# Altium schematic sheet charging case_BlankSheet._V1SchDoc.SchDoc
size 431 x 279 mm; Date: Not shown in title block; ApprovedBy: Not shown in title block; CheckedBy: Not shown in title block; Author: Not shown in title block; CompanyName: Not shown in title block; Engineer: Not shown in title block; Organization: Not shown in title block; Address1: Not shown in title block; Address2: Not shown in title block; Address3: Not shown in title block; Address4: Not shown in title block; DocumentNumber: 1; Revision: Use project parameter SCH_Rev; SheetNumber: 2; SheetTotal: 3; PageSetup: Record=PageOptions¦CenterHorizontal=True¦CenterVertical=True¦PrintScale=1.00¦XCorrection=1.00¦YCorrection=1.00¦PrintKind=0¦BorderSize=5000000¦LeftOffset=0¦BottomOffset=0¦Orientation=2¦PaperLength=1000¦PaperWidth=1000¦Scale=100¦PaperSource=15¦PrintQuality=600¦MediaType=1¦DitherType=10¦PaperKind=Letter¦PrintScaleMode=1
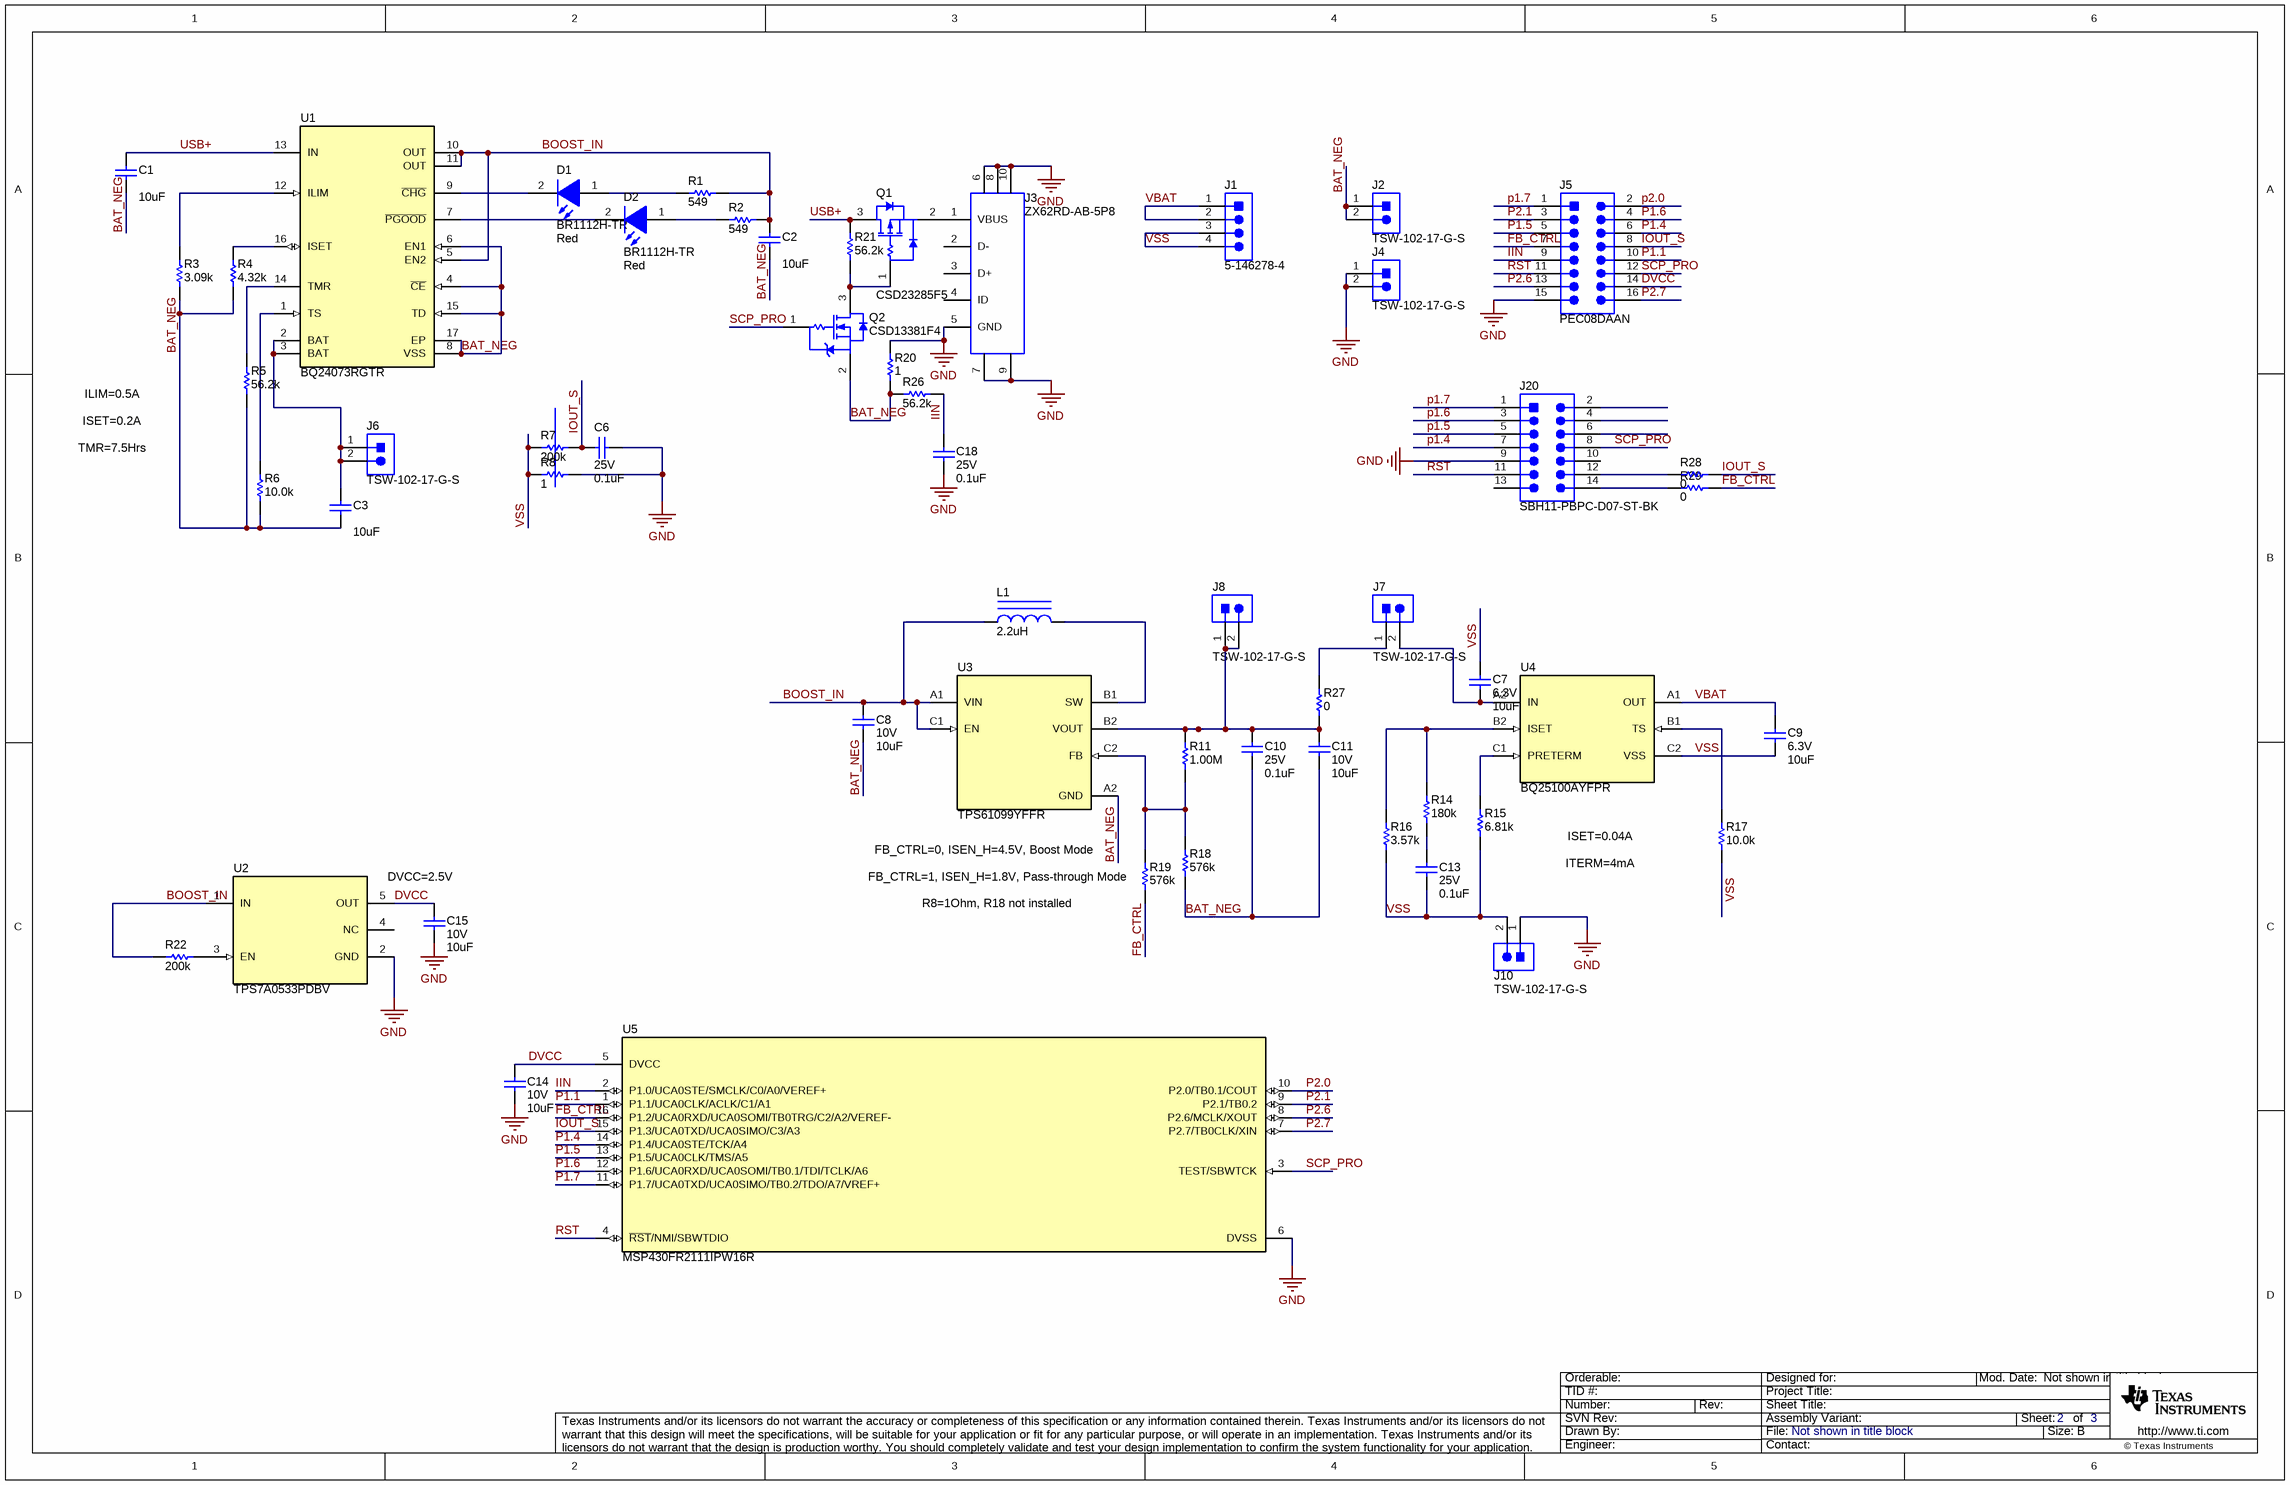
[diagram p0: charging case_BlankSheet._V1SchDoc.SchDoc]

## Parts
C1  ValueDisplayed: 10uF  [0603]  (hidden comment: GRM188Z71A106MA73D)
C2  ValueDisplayed: 10uF  [0603]  (hidden comment: GRM188Z71A106MA73D)
C3  ValueDisplayed: 10uF  [0603]  (hidden comment: GRM188Z71A106MA73D)
C6  VDC_V: 25V  ValueDisplayed: 0.1uF  [0603]  (hidden comment: 06033D104KAT2A)
C7  VDC_V: 6.3V  ValueDisplayed: 10uF  [0402_070]  (hidden comment: C1005X5R0J106M050BC)
C8  VDC_V: 10V  ValueDisplayed: 10uF  [0603]  (hidden comment: GRM188Z71A106MA73D)
C9  VDC_V: 6.3V  ValueDisplayed: 10uF  [0402_070]  (hidden comment: C1005X5R0J106M050BC)
C10  VDC_V: 25V  ValueDisplayed: 0.1uF  [0603]  (hidden comment: 06033D104KAT2A)
C11  VDC_V: 10V  ValueDisplayed: 10uF  [0603]  (hidden comment: GRM188Z71A106MA73D)
C13  VDC_V: 25V  ValueDisplayed: 0.1uF  [0402]  (hidden comment: GRM155R61E104KA87D)
C14  VDC_V: 10V  ValueDisplayed: 10uF  [0603]  (hidden comment: GRM188Z71A106MA73D)
C15  VDC_V: 10V  ValueDisplayed: 10uF  [0603]  (hidden comment: GRM188Z71A106MA73D)
C18  VDC_V: 25V  ValueDisplayed: 0.1uF  [0603]  (hidden comment: 06033D104KAT2A)
D1  BR1112H-TR  value Red  [BR1112H_Red]
D2  BR1112H-TR  value Red  [BR1112H_Red]
J1  5-146278-4  [TE_5-146278-4]
J2  TSW-102-17-G-S  [Samtec_TSW-102-17-x-S]
J3  ZX62RD-AB-5P8  [Hirose_ZX62RD-AB-5P8]
J4  TSW-102-17-G-S  [Samtec_TSW-102-17-x-S]
J5  PEC08DAAN  [Sullins_xxC08DAAN]
J6  TSW-102-17-G-S  [Samtec_TSW-102-17-x-S]
J7  TSW-102-17-G-S  [Samtec_TSW-102-17-x-S]
J8  TSW-102-17-G-S  [Samtec_TSW-102-17-x-S]
J10  TSW-102-17-G-S  [Samtec_TSW-102-17-x-S]
J20  SBH11-PBPC-D07-ST-BK  [CONN_SBH11-PBPC-D07-ST-BK]
L1  ValueDisplayed: 2.2uH  [DFE252012C]  (hidden comment: DFE252012F-2R2M=P2)
Q1  CSD23285F5  [YJK0003A]
Q2  CSD13381F4  [YJC0003A]
R1  ValueDisplayed: 549  [0603]  (hidden comment: RT0603DRE07549RL)
R2  ValueDisplayed: 549  [0603]  (hidden comment: RT0603DRE07549RL)
R3  ValueDisplayed: 3.09k  [0603]  (hidden comment: RC0603FR-073K09L)
R4  ValueDisplayed: 4.32k  [0603]  (hidden comment: RC0603FR-074K32L)
R5  ValueDisplayed: 56.2k  [0603]  (hidden comment: RC0603FR-0756K2L)
R6  ValueDisplayed: 10.0k  [0603]  (hidden comment: RC0603FR-0710KL)
R7  ValueDisplayed: 200k  [0603]  (hidden comment: RG1608P-204-B-T5)
R8  ValueDisplayed: 1  [1206]  (hidden comment: CRM1206-JW-1R0ELF)
R11  ValueDisplayed: 1.00M  [0603]  (hidden comment: MCT06030C1004FP500)
R14  ValueDisplayed: 180k  [0402]  (hidden comment: RC0402FR-07180KL)
R15  ValueDisplayed: 6.81k  [0402]  (hidden comment: RC0402FR-076K81L)
R16  ValueDisplayed: 3.57k  [0402]  (hidden comment: RC0402FR-073K57L)
R17  ValueDisplayed: 10.0k  [0402]  (hidden comment: RC0402FR-0710KL)
R18  ValueDisplayed: 576k  [0603]  (hidden comment: RC0603FR-07576KL)
R19  ValueDisplayed: 576k  [0603]  (hidden comment: RC0603FR-07576KL)
R20  ValueDisplayed: 1  [1206]  (hidden comment: CRM1206-JW-1R0ELF)
R21  ValueDisplayed: 56.2k  [0603]  (hidden comment: RC0603FR-0756K2L)
R22  ValueDisplayed: 200k  [0603]  (hidden comment: RG1608P-204-B-T5)
R26  ValueDisplayed: 56.2k  [0603]  (hidden comment: RC0603FR-0756K2L)
R27  ValueDisplayed: 0  [0603]  (hidden comment: RMCF0603ZT0R00)
R28  ValueDisplayed: 0  [0603]  (hidden comment: RMCF0603ZT0R00)
R29  ValueDisplayed: 0  [0603]  (hidden comment: RMCF0603ZT0R00)
U1  PartNumber: BQ24073RGTR  [RGT0016C]  (hidden comment: BQ24230RGTR)
U2  TPS7A0533PDBV  [DBV0005A_N]
U3  TPS61099YFFR  [YFF0006AFAD]
U4  BQ25100AYFPR  [YFP0006AFAV]
U5  MSP430FR2111IPW16R  [PW0016A_L]

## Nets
GND: C6.1 C14.2 C15.2 C18.2 J3.5(GND) J3.6 J3.7 J3.8 J3.9 J3.10 J4.1 J4.2 J5.15 J10.1 J20.9 R8.2 R20.2 U2.2(GND) U5.6(DVSS)
BAT_NEG: C1.2 C2.2 C3.2 C8.2 C10.2 C11.2 J2.1 J2.2 Q2.2(S) R3.1 R4.1 R5.1 R6.1 R18.1 R20.1 R26.2 U1.4(~{CE}) U1.6(EN1) U1.8(VSS) U1.15(TD) U1.17(EP) U3.A2(GND)
BOOST_IN: C2.1 C8.1 L1.1 R1.1 R2.1 R22.2 U1.5(EN2) U1.10(OUT) U1.11(OUT) U2.1(IN) U3.A1(VIN) U3.C1(EN)
DVCC: C14.1 C15.1 J5.14 U2.5(OUT) U5.5(DVCC)
FB_CTRL: J5.7 R19.1 R29.1 U5.16(P1.2/UCA0RXD/UCA0SOMI/TB0TRG/C2/A2/VEREF-)
IIN: C18.1 J5.9 R26.1 U5.2(P1.0/UCA0STE/SMCLK/C0/A0/VEREF+)
IOUT_S: C6.2 J5.8 R7.1 R28.1 U5.15(P1.3/UCA0TXD/UCA0SIMO/C3/A3)
P1.1: J5.10 U5.1(P1.1/UCA0CLK/ACLK/C1/A1)
P1.4: J5.6 J20.7 U5.14(P1.4/UCA0STE/TCK/A4)
P1.5: J5.5 J20.5 U5.13(P1.5/UCA0CLK/TMS/A5)
P1.6: J5.4 J20.3 U5.12(P1.6/UCA0RXD/UCA0SOMI/TB0.1/TDI/TCLK/A6)
P1.7: J5.1 J20.1 U5.11(P1.7/UCA0TXD/UCA0SIMO/TB0.2/TDO/A7/VREF+)
P2.0: J5.2 U5.10(P2.0/TB0.1/COUT)
P2.1: J5.3 U5.9(P2.1/TB0.2)
P2.6: J5.13 U5.8(P2.6/MCLK/XOUT)
P2.7: J5.16 U5.7(P2.7/TB0CLK/XIN)
RST: J5.11 J20.11 U5.4(~{RST}/NMI/SBWTDIO)
SCP_PRO: J5.12 J20.8 Q2.1(G) U5.3(TEST/SBWTCK)
USB+: C1.1 Q1.3(D) R21.2 U1.13(IN)
VBAT: C9.1 J1.1 J1.2 U4.A1(OUT)
VSS: C7.1 C9.2 C13.2 J1.3 J1.4 J10.2 R7.2 R8.1 R15.1 R16.1 R17.1 U4.C2(VSS)
NetC3_1: C3.1 J6.1 J6.2 U1.2(BAT) U1.3(BAT)
NetC7_2: C7.2 J7.2 U4.A2(IN)
NetC10_1: C10.1 C11.1 J8.1 J8.2 R11.2 R27.1 U3.B2(VOUT)
NetC13_1: C13.1 R14.1
NetD1_1: D1.1(A) R1.2
NetD1_2: D1.2(K) U1.9(~{CHG})
NetD2_1: D2.1(A) R2.2
NetD2_2: D2.2(K) U1.7(~{PGOOD})
NetJ3_1: J3.1(VBUS) Q1.2(S)
NetJ7_1: J7.1 R27.2
NetJ20_12: J20.12 R28.2
NetJ20_14: J20.14 R29.2
NetL1_2: L1.2 U3.B1(SW)
NetQ1_1: Q1.1(G) Q2.3(D) R21.1
NetR3_2: R3.2 U1.12(ILIM)
NetR4_2: R4.2 U1.16(ISET)
NetR5_2: R5.2 U1.14(TMR)
NetR6_2: R6.2 U1.1(TS)
NetR11_1: R11.1 R18.2 R19.2 U3.C2(FB)
NetR14_2: R14.2 R16.2 U4.B2(ISET)
NetR15_2: R15.2 U4.C1(PRETERM)
NetR17_2: R17.2 U4.B1(TS)
NetR22_1: R22.1 U2.3(EN)

Not connected (* = marked no-connect by the designer): J3 2(D-) 3(D+) 4(ID); J20 2 4 6 10 13; U2 4(NC)

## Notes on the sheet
- ILIM=0.5A
- ISET=0.2A
- TMR=7.5Hrs
- ISET=0.04A
- DVCC=2.5V
- FB_CTRL=0, ISEN_H=4.5V, Boost Mode
- (near R19) FB_CTRL=1, ISEN_H=1.8V, Pass-through Mode
- R8=1Ohm, R18 not installed
- ITERM=4mA

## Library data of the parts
C1 = CMP-0007497-5: CAP, CERM, 10 uF, 10 V, +/- 20%, X7R, 0603; Manufacturer: MuRata; TaMin_C: -55°C; Polarized: N; SizeAreaWB_mm2: 4.68; Value1: Unknown; U/M: EA; Value: 10uF; TaMax_C: 125°C; SizeZ_mm: 1; SizeX_mm: 1.6; SizeY_mm: 0.8; Value2: 10V; SizeArea_mm2: 1.28; Cap_F: 10µF; AEC Category: Q200
C2 C3 = CMP-0007497-5: CAP, CERM, 10 uF, 10 V, +/- 20%, X7R, 0603; Manufacturer: MuRata; TaMin_C: -55°C; Polarized: N; SizeAreaWB_mm2: 4.68; Value1: Unknown; U/M: EA; Value: 10uF; TaMax_C: 125°C; SizeZ_mm: 1; SizeX_mm: 1.6; SizeY_mm: 0.8; Value2: 10V; SizeArea_mm2: 1.28; CompType: Capacitor; Cap_F: 10µF; AEC Category: Q200
C6 C10 C18 = CMP-0006758-5: CAP, CERM, 0.1 uF, 25 V, +/- 10%, X5R, 0603; Manufacturer: AVX; TaMin_C: -55°C; ESR_ohm: 0.048; Polarized: N; SizeAreaWB_mm2: 4.68; Value1: 0.048 ohm; U/M: EA; Value: 0.1uF; TaMax_C: 85°C; SizeZ_mm: 1; SizeX_mm: 1.6; SizeY_mm: 0.8; SizeArea_mm2: 1.28; Cap_F: 100nF; IRMS_A: 5.3dA; AEC Category: Q200
C7 = CMP-0006257-2: CAP, CERM, 10 uF, 6.3 V, +/- 20%, X5R, 0402; Manufacturer: TDK; TaMin_C: -55°C; ESR_ohm: 3.019m; Polarized: N; SizeAreaWB_mm2: 3; Value1: 0.003019 ohm; U/M: EA; Value: 10uF; TaMax_C: 85°C; SizeZ_mm: 0.7; SizeX_mm: 1; SizeY_mm: 0.5; Cap_F: 10µF; IRMS_A: 2.87803A; AEC Category: Q200
C8 C11 C14 C15 = CMP-0007497-5: CAP, CERM, 10 uF, 10 V, +/- 20%, X7R, 0603; Manufacturer: MuRata; TaMin_C: -55°C; Polarized: N; SizeAreaWB_mm2: 4.68; Value1: Unknown; U/M: EA; Value: 10uF; TaMax_C: 125°C; SizeZ_mm: 1; SizeX_mm: 1.6; SizeY_mm: 0.8; SizeArea_mm2: 1.28; Cap_F: 10µF; AEC Category: Q200
C9 = CMP-0006257-2: CAP, CERM, 10 uF, 6.3 V, +/- 20%, X5R, 0402; Manufacturer: TDK; TaMin_C: -55°C; ESR_ohm: 3.019m; Polarized: N; SizeAreaWB_mm2: 3; Value1: 0.003019 ohm; U/M: EA; Value: 10uF; TaMax_C: 85°C; SizeZ_mm: 0.7; SizeX_mm: 1; SizeY_mm: 0.5; CompType: Capacitor; Cap_F: 10µF; IRMS_A: 2.87803A; AEC Category: Q200
C13 = CMP-0006607-2: CAP, CERM, 0.1 uF, 25 V, +/- 10%, X5R, 0402; Manufacturer: MuRata; TaMin_C: -55°C; Polarized: N; SizeAreaWB_mm2: 3; Value1: Unknown; U/M: EA; Value: 0.1uF; TaMax_C: 85°C; SizeZ_mm: 0.6; SizeX_mm: 1; SizeY_mm: 0.5; CompType: Capacitor; Cap_F: 100nF; AEC Category: Q200
D1 D2 = CMP-0067678-1: LED, Red, SMD; Manufacturer: Stanley Electric Co., LTD; Io_A: 20mA; Power_TotalModule: 57.5mW; Green_Lifecycle: Not Set; SizeAreaWB_mm2: 6.75; Vr_V: 4V; Tjmax_C: 85°C; Green_REACh: Incomplete; Value1: 0.0575W; U/M: EA; Angle: 150.0; SizeZ_mm: 0.9; SizeX_mm: 2.0; SizeY_mm: 1.25; Ir_A: 100µA; Vf_V: 1.7V; SizeArea_mm2: 2.5
J1 = CMP-0054950-1: Header, 100mil, 4x1, Tin, TH; Manufacturer: TE Connectivity; CNHeader: TRUE; Green_Lifecycle: Active; Green_REACh: Passed; CT: FALSE
J2 J4 J6-J8 J10 = CMP-0077742-1: Header, 2.54mm, 2x1, Gold, TH; Manufacturer: Samtec; Pitch_mm: 2.54; Gender: Male; Cert_CSA: Y; Shrouded: N; Row_Count: 1
J3 = CMP-0075126-1: Connector, Receptacle, Micro-USB Type AB, R/A, Bottom Mount SMT; Manufacturer: Hirose Electric Co. Ltd.; CNHeader: False; Gender: Female; CompType: USB; Row_Count: 1; Pitch_mm: 0.65; CT: True
J5 = CMP-0054579-1: Header, 2.54 mm, 8x2, Tin, Vertical, TH; Manufacturer: Sullins Connector Solutions; CNHeader: TRUE; Current_A: 3A; Green_Lifecycle: Not Set; Shrouded: N; Gender: Male; Green_REACh: Incomplete; Voltage_V: 1.8kV; Row_Count: 2; RowSpacing_mm: 2.54; CT: FALSE; Cert_UL: Y
J20 = CMP-0054695-1: Header (shrouded), 100 mil, 7x2, Gold, TH; Manufacturer: Sullins Connector Solutions; CT: FALSE; Green_REACh: Incomplete; Green_Lifecycle: Not Set
L1 = CMP-0058932-1: Inductor, Shielded, Powdered Iron, 2.2 uH, 2.3 A, 0.082 ohm, SMD; Manufacturer: MuRata Toko; Isat: 3.3A @ 30% inductance drop; Irms: 2.3A @ 40C rise; SizeAreaWB_mm2: 11.84; DCR_ohm: 0.082; Value: 2.2uH; Imax_A: 2.3A; SizeZ_mm: 1.2; SizeX_mm: 2.7; SizeY_mm: 2.2; SizeArea_mm2: 5.94; Ind_H: 2.2µH; AEC Qualified: N; AEC Category: Q200
Q1 = CMP-0000021-2: MOSFET, P-CH, -12 V, -3.3 A, YJK0003A (PICOSTAR-3); Alternate Manufacturer: None; Manufacturer: Texas Instruments; SizeZ_mm: 0.35; ChType: P; Value2: 3.2 nC; Value1: 0.03; VdsMax_V: -12V; SizeX_mm: 1.49; SizeY_mm: 0.73; Vgs_V: -6V; AEC Qualified: N; Value: -12V; Rdson45_ohm: 0.035; SizeArea_mm2: 1.0877; AEC Category: Q101; IdsMax_A: -3.3A; SizeAreaWB_mm2: 4.3077; U/M: EA; QgTyp_nC: 3.2
Q2 = CMP-0000197-1: MOSFET, N-CH, 12 V, 2.1 A, YJC0003A (PICOSTAR-3); Alternate Manufacturer: None; Manufacturer: Texas Instruments; SizeZ_mm: 0.35; ChType: N; Value2: 1.06 nC; Value1: 0.1; VdsMax_V: 12V; SizeX_mm: 1.035; SizeY_mm: 0.635; Vgs_V: 8V; Value: 12V; Rdson45_ohm: 1.4d; SizeArea_mm2: 0.657225; AEC Category: Q101; IdsMax_A: 2.1A; SizeAreaWB_mm2: 3.327225; U/M: EA; QgTyp_nC: 1.06
R1 = CMP-0025400-3: RES, 549, 0.5%, 0.1 W, 0603; Manufacturer: Yageo America; Power_W: 100mW; TempCo: 50 ppm/C; Value_Code: 549R; U/M: EA; Value: 549; EIA_Code: E192; SizeX_mm: 1.6; SizeY_mm: 0.8; SizeZ_mm: 1; Value2: 0.1W; SizeArea_mm2: 1.28; CompType: Resistor; VDC_V: 75V; AEC Category: Q200
R2 = CMP-0025400-3: RES, 549, 0.5%, 0.1 W, 0603; Manufacturer: Yageo America; Power_W: 100mW; TempCo: 50 ppm/C; Value_Code: 549R; U/M: EA; Value: 549; EIA_Code: E192; SizeX_mm: 1.6; SizeY_mm: 0.8; SizeZ_mm: 1; Value2: 0.1W; SizeArea_mm2: 1.28; VDC_V: 75V; AEC Category: Q200
R3 = CMP-0023077-3: RES, 3.09 k, 1%, 0.1 W, 0603; Manufacturer: Yageo America; Power_W: 100mW; TempCo: 200 ppm/C; Value_Code: 3k09; U/M: EA; Value: 3.09k; EIA_Code: E96; SizeX_mm: 1.6; SizeY_mm: 0.8; SizeZ_mm: 1; Value2: 0.1W; SizeArea_mm2: 1.28; VDC_V: 150V; AEC Category: Q200
R4 = CMP-0023147-3: RES, 4.32 k, 1%, 0.1 W, 0603; Manufacturer: Yageo America; Power_W: 100mW; TempCo: 200 ppm/C; Value_Code: 4k32; U/M: EA; Value: 4.32k; EIA_Code: E96; SizeX_mm: 1.6; SizeY_mm: 0.8; SizeZ_mm: 1; Value2: 0.1W; SizeArea_mm2: 1.28; VDC_V: 150V; AEC Category: Q200
R5 R21 R26 = CMP-0023186-3: RES, 56.2 k, 1%, 0.1 W, 0603; Manufacturer: Yageo America; Power_W: 100mW; TempCo: 200 ppm/C; Value_Code: 56k2; U/M: EA; Value: 56.2k; EIA_Code: E96; SizeX_mm: 1.6; SizeY_mm: 0.8; SizeZ_mm: 1; Value2: 0.1W; SizeArea_mm2: 1.28; VDC_V: 150V; AEC Category: Q200
R6 = CMP-0022746-3: RES, 10.0 k, 1%, 0.1 W, 0603; Manufacturer: Yageo America; Power_W: 100mW; TempCo: 200 ppm/C; Value_Code: 10k0; U/M: EA; Value: 10.0k; EIA_Code: E96; Res_ohm: 10k; SizeX_mm: 1.6; SizeY_mm: 0.8; SizeZ_mm: 1; Value2: 0.1W; SizeArea_mm2: 1.28; CompType: Resistor; VDC_V: 150V; AEC Category: Q200
R7 R22 = CMP-0023465-3: RES, 200 k, 0.1%, 0.1 W, 0603; Manufacturer: Susumu Co Ltd; Power_W: 100mW; TempCo: 25 ppm/C; U/M: EA; Value: 200k; EIA_Code: E192; SizeX_mm: 1.6; SizeY_mm: 0.8; SizeZ_mm: 1; Value2: 0.1W; SizeArea_mm2: 1.28; CompType: Resistor; VDC_V: 75V; AEC Category: Q200
R8 R20 = CMP-0018745-2: RES, 1.0, 5%, 0.5 W, 1206; Manufacturer: Bourns; Power_W: 500mW; TempCo: 150 ppm/C; Value_Code: 1R00; U/M: EA; Value: 1.0; EIA_Code: E24; SizeX_mm: 3.2; SizeY_mm: 1.6; SizeZ_mm: 1.35; Value2: 0.5W; SizeArea_mm2: 5.12; CompType: Resistor; VDC_V: 1V; AEC Category: Q200
R11 = CMP-0022731-2: RES, 1.00 M, 1%, 0.125 W, 0603; Manufacturer: Vishay/Beyschlag; Power_W: 125mW; TempCo: 50 ppm/C; Value_Code: 1M00; U/M: EA; Value: 1.00Meg; EIA_Code: E96; Res_ohm: 1M; SizeX_mm: 1.6; SizeY_mm: 0.8; SizeZ_mm: 1; Value2: 0.125W; SizeArea_mm2: 1.28; CompType: Resistor; AEC Qualified: N; VDC_V: 75V; AEC Category: Q200
R14 = CMP-0026723-1: RES, 180 k, 1%, 0.063 W, 0402; Manufacturer: Yageo America; Power_W: 63mW; TempCo: 100 ppm/C; U/M: EA; Value: 180k; SizeX_mm: 1; SizeY_mm: 0.5; SizeZ_mm: 0.6; Value2: 0.063W; AEC Qualified: N; VDC_V: 50V; AEC Category: Q200
R15 = CMP-0078787-1: RES, 6.81 k, 1%, 0.063 W, 0402; Manufacturer: Yageo America; Value_Code: 6k81; SizeArea_mm2: 0.5; AEC Qualified: N; AEC Category: Q200; Value: 6.81k; SizeZ_mm: 0.6; EIA_Code: E96; TempCo: 100 ppm/C; Power_W: 63mW; VDC_V: 50V; Value2: 0.063W; SizeX_mm: 1
R16 = CMP-0078784-1: RES, 3.57 k, 1%, 0.063 W, 0402; Manufacturer: Yageo America; Value_Code: 3k57; SizeArea_mm2: 0.5; AEC Qualified: N; AEC Category: Q200; Value: 3.57k; SizeZ_mm: 0.6; EIA_Code: E96; TempCo: 100 ppm/C; Power_W: 63mW; VDC_V: 50V; Value2: 0.063W; SizeX_mm: 1
R17 = CMP-0078669-1: RES, 10.0 k, 1%, 0.063 W, 0402; Manufacturer: Yageo America; Power_W: 63mW; Green_Lifecycle: Active; TempCo: 100 ppm/C; Value_Code: 10k0; Green_REACh: Passed; Value: 10.0k; EIA_Code: E96; Res_ohm: 10k; SizeX_mm: 1; SizeY_mm: 0.5; SizeZ_mm: 0.6; Value2: 0.063W; AEC Qualified: N; AEC Category: Q200
R18 R19 = CMP-0023189-2: RES, 576 k, 1%, 0.1 W, 0603; Manufacturer: Yageo America; Power_W: 100mW; TempCo: 200 ppm/C; U/M: EA; Value: 576k; EIA_Code: E96; SizeX_mm: 1.6; SizeY_mm: 0.8; SizeZ_mm: 1; Value2: 0.1W; SizeArea_mm2: 1.28; VDC_V: 150V; AEC Category: Q200
R27-R29 = CMP-0023343-3: RES, 0, 1%, 0.1 W, AEC-Q200 Grade 0, 0603; Manufacturer: Stackpole Electronics Inc; Power_W: 100mW; TempCo: ppm/C; U/M: EA; Value: 0; SizeX_mm: 1.6; SizeY_mm: 0.8; SizeZ_mm: 1; Value2: 0.1W; SizeArea_mm2: 1.28; AEC Qualified: Y; AEC Category: Q200
U1 = CMP-0034120-2: USB Friendly 0.5 A Li+ Charger with Dynamic Power Management, 6.6 V OVP, 4.3 V, -40 to 85 degC, 16-pin QFN (RGT), Green (RoHS & no Sb/Br); Manufacturer: Texas Instruments; SubFamily: Battery Charge Management; Vin(Min)(V): 4.3; NiCd: N
U2 = CMP-0013051-2: 1uA IQ, 200 mA, Ultralow IQ Low-Dropout Regulator, DBV0005A (SOT-5); Manufacturer: Texas Instruments; SizeX_mm: 2.8; SizeY_mm: 2.9; CompType: IC; SizeZ_mm: 1.45; SizeArea_mm2: 8.12; SizeAreaWB_mm2: 14.82; U/M: EA
U3 = CMP-0074075-1: Synchronous Boost Converter with 800 nA Ultra-Low Quiescent Current, YFF0006AFAD (DSBGA-6); Alternate PartNumber: TPS61099YFFT; Alternate Manufacturer: Texas Instruments; SizeAreaWB_mm2: 4.193784; U/M: EA; SizeZ_mm: 0.625; SizeX_mm: 0.884; SizeY_mm: 1.226; SizeArea_mm2: 1.083784; CompType: IC
U4 = CMP-0076143-1: 250-mA Single Cell Li-Ion Battery Charger, 1mA termination, 75nA Battery leakage, YFP0006AFAV (DSBGA-6); Manufacturer: Texas Instruments; Alternate PartNumber: BQ25100AYFPT; SizeAreaWB_mm2: 4.84664; SizeArea_mm2: 1.38864; SizeZ_mm: 0.5; SizeY_mm: 1.578; U/M: EA; CompType: IC; SizeX_mm: 0.88
U5 = CMP-0076600-1: 16 MHz Ultra-Low-Power Microcontroller With 4 KB FRAM, 1 KB SRAM, 12 IO, 8 ch ADC10, PW0016A (TSSOP-16); Manufacturer: Texas Instruments; SizeAreaWB_mm2: 58.8; SizeArea_mm2: 32.0; SizeZ_mm: 1.2; SizeY_mm: 5.0; U/M: EA; CompType: IC; SizeX_mm: 6.4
